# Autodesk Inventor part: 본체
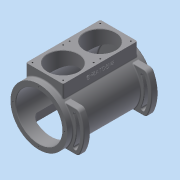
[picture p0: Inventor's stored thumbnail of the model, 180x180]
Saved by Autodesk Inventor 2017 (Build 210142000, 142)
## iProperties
Created: 2016-11
Part Number: 본체
Material: 알루미늄 6061
Document SubType Name: Modeling
Designer: mduedu
Density: 2.71 g/cm^3
Appearance: 기본값
Mass: 2446.31 g
Surface Area: 1767.27 cm^2
Volume: 902.698 cm^3
Author: mduedu
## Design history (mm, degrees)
sketch "스케치1"
  geometry: C1 r 65 at (0, 0); 1 further point
  constraints: 1 centre point, 1 coincident
  dimensions: "d119" = 130 diameter of C1
extrude "돌출1" new body sketch "스케치1" distance "d3" = 98; taper "d4" = 0 deg; dims "d132" = 97, "d133" = 0
feature "쉘1" dims "d120" = 12, "d134" = 8
node "작업 평면2"
sketch "스케치13"
  geometry: L1 (42.5, 85)-(-42.5, 85); L2 (-42.5, 85)-(-42.5, -85); L3 (-42.5, -85)-(42.5, -85); L4 (42.5, -85)-(42.5, 85); 2 further points
  constraints: 8 end point, 2 parallel, 1 horizontal, 1 midpoint, 1 perpendicular, 1 vertical alignment
  dimensions: "d122" = 170 distance of L1.end L2.end; "d124" = 85 distance of L2.end L3.end; "d125" = 85 distance from line of point (0, 0) L1 (= 0.5 x d122)
extrude "돌출11" join sketch "스케치13" stored distance "d126" = 10; taper "d127" = 0 deg
sketch "스케치14"
  geometry: L1 (65, 97)-(-65, 97) reference; C1 r 35 at (0, 42.5); 1 further point
  constraints: 1 centre point, 1 vertical alignment
  dimensions: "d128" = 70 diameter of C1; "d129" = 54.5 distance from line of C1.centre L1
extrude "돌출12" cut sketch "스케치14" stored distance "d130" = 10; taper "d131" = 0 deg
sketch "스케치15"
  geometry: C1 r 53 at (0, 0) reference; 1 further point
extrude "돌출13" cut sketch "스케치15" stored distance "d135" = 10; taper "d136" = 0 deg
chamfer "모따기1" distance "d54" = 1; stored, may be unused: second distance "d55" = 2, angle "d56" = 45 deg
sketch "스케치8"
  geometry: C1 r 30 at (0, 0); C2 r 65 at (0, 0) reference; 1 further point
  constraints: 1 centre point, 1 concentric
  dimensions: "d57" = 60 diameter of C1
extrude "돌출8" join sketch "스케치8" distance "d58" = 14; taper "d59" = 0 deg
hole "구멍3" diameter "d62" = 41; stored, may be unused: countersink angle "d66" = 90 deg, drill point angle "d68" = 0 deg; dims "d63" = 6, "d64" = 47, "d65" = 14, "d67" = 17, "d195" = 10, "d196" = 10
fillet "모깎기11" dims "d69" = 3
fillet "모깎기12" dims "d70" = 3
fillet "모깎기13" dims "d71" = 0.3
chamfer "모따기2" distance "d72" = 1; stored, may be unused: second distance "d73" = 2, angle "d74" = 45 deg
node "작업 평면3"
sketch "스케치16"
  geometry: L1 (-42.5, -80)-(47.5, -80); L2 (-42.5, -80)-(21.14, -16.36); L3 (-42.5, -80)-(21.14, -143.64); L4 (3.462, -34.038)-(34.879, -34.038); L5 (3.462, -125.962)-(34.879, -125.962); A1 r 65 centre (-42.5, -80) between (3.462, -34.038) and (3.462, -125.962) reference; A2 r 90 centre (-42.5, -80) between (34.879, -125.962) and (34.879, -34.038); A3 r 90 centre (-42.5, -80) between (34.879, -34.038) and (34.879, -125.962); A4 r 65 centre (-42.5, -80) between (3.462, -125.962) and (3.462, -34.038); 1 further point
  constraints: 11 point on circle, 10 end point, 3 centre point, 2 parallel, 2 point on line, 1 coincident, 1 horizontal
  dimensions: "d140" = 45 deg angle of L3 L1; "d141" = 45 deg angle of L2 L1; "d142" = 25 radial gap between concentric circles of A1 A2
extrude "돌출14" join sketch "스케치16" distance "d143" = 15; taper "d144" = 0 deg
sketch "스케치17"
  geometry: L1 (-42.5, -80)-(34.414, -80); L2 (-42.5, -80)-(27.208, -47.495); L3 (-42.5, -80)-(27.208, -112.505); L4 (34.879, -34.038)-(3.462, -34.038) reference; L5 (3.462, -125.962)-(34.879, -125.962) reference; A1 r 65 centre (-42.5, -80) between (3.462, -34.038) and (3.462, -125.962) reference; A2 r 76.914 centre (-42.5, -80) between (19.17, -125.962) and (19.17, -34.038); A3 r 4 centre (27.208, -47.495) between (23.582, -49.185) and (30.833, -45.804); A4 r 4 centre (27.208, -112.505) between (30.833, -114.196) and (23.582, -110.815); A5 r 80.914 centre (-42.5, -80) between (30.833, -114.196) and (30.833, -45.804); A6 r 72.914 centre (-42.5, -80) between (23.582, -110.815) and (23.582, -49.185); 1 further point
  constraints: 13 point on circle, 6 end point, 5 centre point, 5 coincident, 3 midpoint, 2 point on line, 1 equal radius, 1 horizontal
  dimensions: "d145" = 25 deg angle of L1 L3; "d146" = 25 deg angle of L2 L1; "d147" = 8 diameter of A3
extrude "돌출15" cut sketch "스케치17" stored distance "d150" = 15; taper "d151" = 0 deg
fillet "모깎기17" dims "d152" = 10
fillet "모깎기18" dims "d153" = 2
fillet "모깎기19" dims "d154" = 2
chamfer "모따기4" distance "d155" = 1; stored, may be unused: second distance "d156" = 2, angle "d157" = 45 deg
fillet "모깎기20" dims "d159" = 3
fillet "모깎기21" dims "d160" = 3
fillet "모깎기22" dims "d161" = 3
node "작업 평면4"
sketch "스케치18"
  geometry: L1 (-42.5, 70)-(42.5, 70); L2 (42.5, 70)-(42.5, -70); L3 (42.5, -70)-(-42.5, -70); L4 (-42.5, -70)-(-42.5, 70); 2 further points
  constraints: 8 end point, 2 parallel, 1 horizontal, 1 midpoint, 1 perpendicular, 1 vertical alignment
  dimensions: "d162" = 140 distance of L1.end L2.end; "d164" = 85 distance of L2.end L3.end; "d165" = 70 distance from line of point (0, 0) L1 (= 0.5 x d162)
extrude "돌출16" cut sketch "스케치18" stored distance "d166" = 15; taper "d167" = 0 deg
fillet "모깎기23" dims "d168" = 10
fillet "모깎기24" dims "d173" = 3
sketch "스케치19"
  geometry: 4 further points
  constraints: 4 other
hole "구멍6" sketch "스케치19" at (0, -59), (59, 0), (-59, 0), (0, 59) diameter "d174" = 3.242; stored, may be unused: countersink angle "d178" = 90 deg, drill point angle "d180" = 120 deg; dims "d175" = 8, "d176" = 4, "d177" = 2, "d179" = 10
sketch "스케치20"
  geometry: L1 (35, -77.5)-(-35, -77.5); L2 (-35, -77.5)-(-35, -7.5); L3 (-35, -7.5)-(35, -7.5); L4 (35, -7.5)-(35, -77.5); L5 (35, -77.5)-(-35, -7.5); L6 (-35, -77.5)-(35, -7.5); C1 r 36 at (0, -42.5) reference; 5 further points
  constraints: 12 end point, 4 coincident, 2 midpoint, 2 parallel, 1 horizontal, 1 perpendicular
  dimensions: "d181" = 70 distance of L2.end L3.end; "d182" = 70 distance of L1.end L2.end
hole "구멍7" sketch "스케치20" at (-35, -77.5), (-35, -7.5), (35, -7.5), (35, -77.5) diameter "d183" = 3.242; stored, may be unused: countersink angle "d187" = 90 deg, drill point angle "d189" = 118 deg; dims "d184" = 8, "d185" = 4, "d186" = 2, "d188" = 10
sketch "스케치21"
  geometry: L1 (164, 0)-(0, 0) reference; L2 (-3, 0)-(-3, -24.649) reference; 3 further points
  constraints: 1 midpoint, 1 vertical alignment, 1 other
  dimensions: "d190" = 15 distance from line of point (82, -15) L1; "d191" = 85 distance from line of point (82, 0) L2 (derived)
feature "엠보싱2" sketch "스케치21" dims "d3" = 98, "d4" = 0, "d119" = 130, "d132" = 97, "d133" = 0, "d192" = 0.5, "d193" = 0
node "솔리드1"
mirror "대칭5"
mirror "대칭6"
mirror "대칭7"
